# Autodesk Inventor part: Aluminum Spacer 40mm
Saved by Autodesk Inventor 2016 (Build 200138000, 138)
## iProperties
Created: 2015-11
Part Number: Aluminum Spacer 40mm
Material: Generic
Document SubType Name: Modeling
Designer: John
Density: 1 g/cm^3
Appearance: Default
Author: John
Revision Number: ANY
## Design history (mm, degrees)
chamfer "Chamfer1"
body "Solid1"
